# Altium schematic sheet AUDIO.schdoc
size 216 x 160 mm
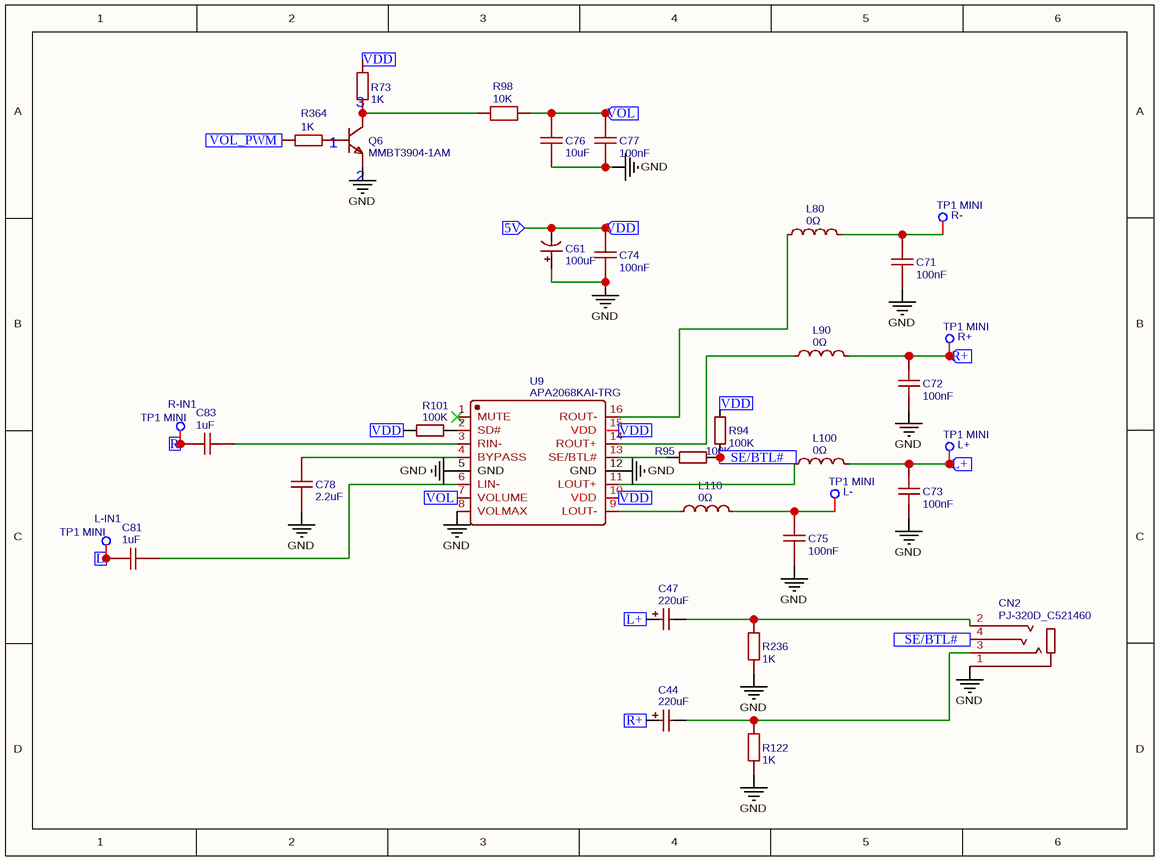
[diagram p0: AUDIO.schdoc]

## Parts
C44  220uF  [CAP-SMD_L3.5-W2.8-R-RD]
C47  220uF  [CAP-SMD_L3.5-W2.8-R-RD]
C61  100uF  [CAP-SMD_L3.2-W1.6]
C71  100nF  [C0402]
C72  100nF  [C0402]
C73  100nF  [C0402]
C74  100nF  [C0402]
C75  100nF  [C0402]
C76  10uF  [C0603]
C77  100nF  [C0402]
C78  2.2uF  [C0402]
C81  1uF  [C0402]
C83  1uF  [C0402]
CN2  PJ-320D_C521460  [MAUDIO-SMD_PJ-320D]
L80  0Ω  [L0402]
L90  0Ω  [L0402]
L100  0Ω  [L0402]
L110  0Ω  [L0402]
L+  TP1 MINI  [TP1 MINI]
L-  TP1 MINI  [TP1 MINI]
L-IN1  TP1 MINI  [TP1 MINI]
Q6  MMBT3904-1AM  [SOT-23-3_L3.0-W1.7-P0.95-LS2.9-BR]
R73  1K  [R0402]
R94  100K  [R0402]
R95  100K  [R0402]
R98  10K  [R0402]
R101  100K  [R0402]
R122  1K  [R0402]
R236  1K  [R0402]
R364  1K  [R0402]
R+  TP1 MINI  [TP1 MINI]
R-  TP1 MINI  [TP1 MINI]
R-IN1  TP1 MINI  [TP1 MINI]
U9  APA2068KAI-TRG  [SOIC-16_L9.9-W3.9-P1.27-LS6.0-BL]

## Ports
5V (in), L (in), L+ (in), R (in), R+ (in), SE/BTL# (in), VDD (in), VOL (in), VOL_PWM (in)

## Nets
GND: C61.1 C71.2 C72.2 C73.2 C74.2 C75.2 C76.2 C77.2 C78.2 CN2.1 Q6.2(E) R122.1 R236.1 U9.5(GND) U9.8(VOLMAX) U9.12(GND)
5V: C61.2 C74.1 R73.2 R94.2 R101.1 U9.10(VDD) U9.15(VDD) ; port VDD, port 5V
L: C81.2 L-IN1.1 ; port L
L+: C47.1 C73.1 L100.2 L+.1 ; port L+
R: C83.2 R-IN1.1 ; port R
R+: C44.1 C72.1 L90.2 R+.1 ; port R+
SE/BTL#: CN2.4 R94.1 R95.2 ; port SE/BTL#
VOL: C76.1 C77.1 R98.1 U9.7(VOLUME) ; port VOL
VOL_PWM: R364.1 ; port VOL_PWM
NetC44_2: C44.2 CN2.3 R122.2
NetC47_2: C47.2 CN2.2 R236.2
NetC71_1: C71.1 L80.2 R-.1
NetC75_1: C75.1 L110.2 L-.1
NetC78_1: C78.1 U9.4(BYPASS)
NetC81_1: C81.1 U9.6(LIN-)
NetC83_1: C83.1 U9.3(RIN-)
NetL80_1: L80.1 U9.16(ROUT-)
NetL90_1: L90.1 U9.14(ROUT+)
NetL100_1: L100.1 U9.11(LOUT+)
NetL110_1: L110.1 U9.9(LOUT-)
NetQ6_1: Q6.1(B) R364.2
NetQ6_3: Q6.3(C) R73.1 R98.2
NetR95_1: R95.1 U9.13(SE/BTL#)
NetR101_2: R101.2 U9.2(SD#)

Not connected (* = marked no-connect by the designer): U9 1(MUTE)*

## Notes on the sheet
- (near R73) 3
- 1
- (near Q6) 2

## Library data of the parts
C44 C47 = 220uF: Manufacturer: AVX; Manufacturer Part: TLJB227M006R0500; nameAlias: Capacitance
C61 = 100uF: Manufacturer: Hunan Xiangyee in S&T; Manufacturer Part: CA45-A6R3K107T; nameAlias: Capacitance; Contributor: LCSC
C71-C75 C77 = 100nF: Manufacturer: YAGEO; Manufacturer Part: CC0402JRX7R6BB104; nameAlias: Capacitance; Contributor: LCSC
C76 = 10uF: Manufacturer: SAMSUNG; Manufacturer Part: CL10A106KP8NNNC; nameAlias: Capacitance
C78 = 2.2uF: Manufacturer: Samsung Electro-Mechanics; Manufacturer Part: CL05A225KQ5NSNC; nameAlias: Capacitance; Contributor: LCSC
C81 C83 = 1uF: Manufacturer: SAMSUNG; Manufacturer Part: CL05A105KA5NQNC; nameAlias: Capacitance
CN2 = PJ-320D_C521460: Manufacturer: USAKRO; Contributor: LCSC
L80 L90 L100 L110 = 0Ω: Manufacturer: FH; Manufacturer Part: CBG100505U000T; nameAlias: Value
L+ L- L-IN1 R+ R- R-IN1 = TP1 MINI: Contributor: Marlon Vinicius
Q6 = MMBT3904-1AM: Manufacturer: (MDD) Jiangsu Yutai Elec; Contributor: LCSC; SMT Type: Extend
R73 R122 R236 R364 = 1K: Manufacturer: YAGEO; Manufacturer Part: AC0402FR-071KL; nameAlias: Resistance (Ohms); Contributor: LCSC; Resistance: 1kΩ
R94 R95 R101 = 100K: Manufacturer: YAGEO; Manufacturer Part: RC0402FR-07100KL; nameAlias: Resistance (Ohms)
R98 = 10K: Manufacturer: PANASONIC; Manufacturer Part: ERJPA2F1002X; nameAlias: Resistance (Ohms); Contributor: LCSC
U9 = APA2068KAI-TRG: Manufacturer: ANPEC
